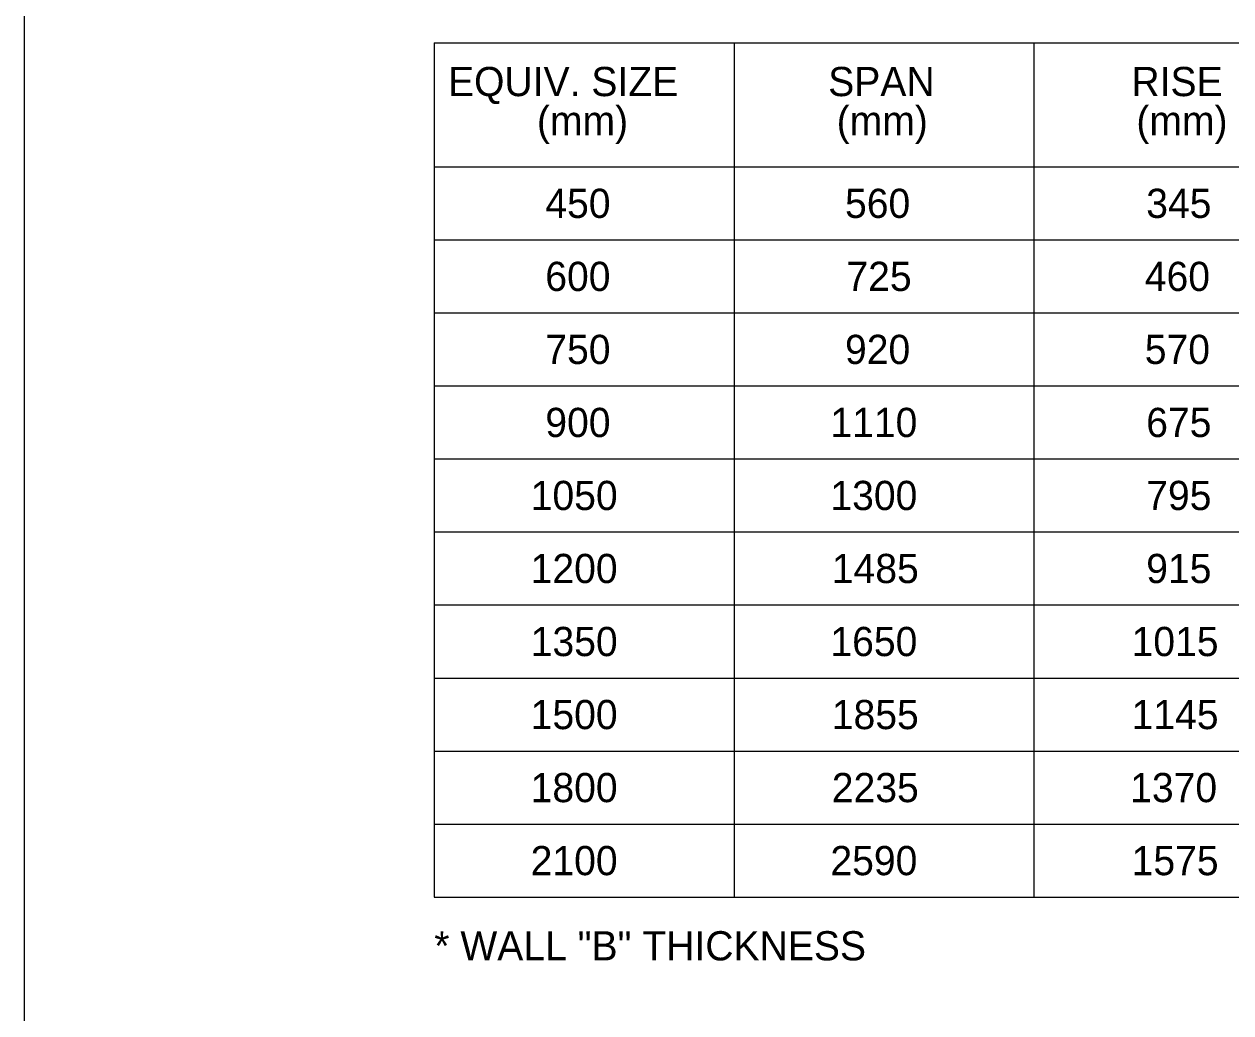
# Model space of a CAD drawing. Extents: x 49991.4 to 50021, y 49987.6 to 50011.4.
# Drawn here: x 50000.336 to 50002.813, y 50006.796 to 50008.827 of the extents above; entities that cross this region are included whole.
import ezdxf

# ---------------------------------------------------------------- set-up
doc = ezdxf.new("R2010")
doc.units = 0
doc.layers.add('Level 1', color=7, linetype='Continuous')
doc.layers.add('Level 2', color=7, linetype='Continuous')

msp = doc.modelspace()

# ---------------------------------------------------------------- linework, layer by layer
at = {"layer": 'Level 1'}
msp.add_lwpolyline([(50008.6146, 50011.2628), (50000.3356, 50011.2628), (50000.3356, 50000.0624), (50008.6146, 50000.0624)], close=True, dxfattribs=at)
at = {"layer": 'Level 2'}
for p, q in [((50001.1776, 50008.788), (50007.9467, 50008.788)), ((50001.1776, 50008.788), (50001.1776, 50007.0334)), ((50001.7929, 50008.788), (50001.7929, 50007.0334)), ((50002.4082, 50008.788), (50002.4082, 50007.0334)), ((50001.1776, 50008.5334), (50007.9467, 50008.5334)), ((50001.1776, 50008.3834), (50007.9467, 50008.3834)), ((50001.1776, 50008.2334), (50007.9467, 50008.2334)), ((50001.1776, 50008.0834), (50007.9467, 50008.0834)), ((50001.1776, 50007.9334), (50007.9467, 50007.9334)), ((50001.1776, 50007.7834), (50007.9467, 50007.7834)), ((50001.1776, 50007.6334), (50007.9467, 50007.6334)), ((50001.1776, 50007.4834), (50007.9467, 50007.4834)), ((50001.1776, 50007.3334), (50007.9467, 50007.3334)), ((50001.1776, 50007.1834), (50007.9467, 50007.1834)), ((50001.1776, 50007.0334), (50007.9467, 50007.0334))]:
    msp.add_line(p, q, dxfattribs=at)

# ---------------------------------------------------------------- texts
for s, p in [('EQUIV. SIZE', (50001.2057, 50008.6786)), ('SPAN', (50001.9862, 50008.6786)), ('RISE', (50002.6086, 50008.6786)), ('(mm)', (50001.3883, 50008.5982)), ('(mm)', (50002.0036, 50008.5982)), ('(mm)', (50002.6188, 50008.5982)), ('450', (50001.4055, 50008.4284)), ('560', (50002.0207, 50008.4284)), ('345', (50002.639, 50008.4284)), ('600', (50001.4054, 50008.2784)), ('725', (50002.0236, 50008.2784)), ('460', (50002.6361, 50008.2784)), ('750', (50001.4055, 50008.1284)), ('920', (50002.0207, 50008.1284)), ('570', (50002.6361, 50008.1284)), ('900', (50001.4055, 50007.9784)), ('1110', (50001.9907, 50007.9784)), ('675', (50002.639, 50007.9784)), ('1050', (50001.3755, 50007.8284)), ('1300', (50001.9907, 50007.8284)), ('795', (50002.639, 50007.8284)), ('1200', (50001.3754, 50007.6784)), ('1485', (50001.9936, 50007.6784)), ('915', (50002.639, 50007.6784)), ('1350', (50001.3755, 50007.5284)), ('1650', (50001.9907, 50007.5284)), ('1015', (50002.609, 50007.5284)), ('1500', (50001.3754, 50007.3784)), ('1855', (50001.9936, 50007.3784)), ('1145', (50002.609, 50007.3784)), ('1800', (50001.3754, 50007.2284)), ('2235', (50001.9936, 50007.2284)), ('1370', (50002.6061, 50007.2284)), ('2100', (50001.3754, 50007.0784)), ('2590', (50001.9907, 50007.0784)), ('1575', (50002.6091, 50007.0784)), ('* WALL "B" THICKNESS', (50001.1776, 50006.9034))]:
    msp.add_text(s, height=0.06, dxfattribs=at).set_placement(p)

doc.saveas('drawing.dxf')
